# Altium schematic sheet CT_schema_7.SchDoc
size 278 x 170 mm
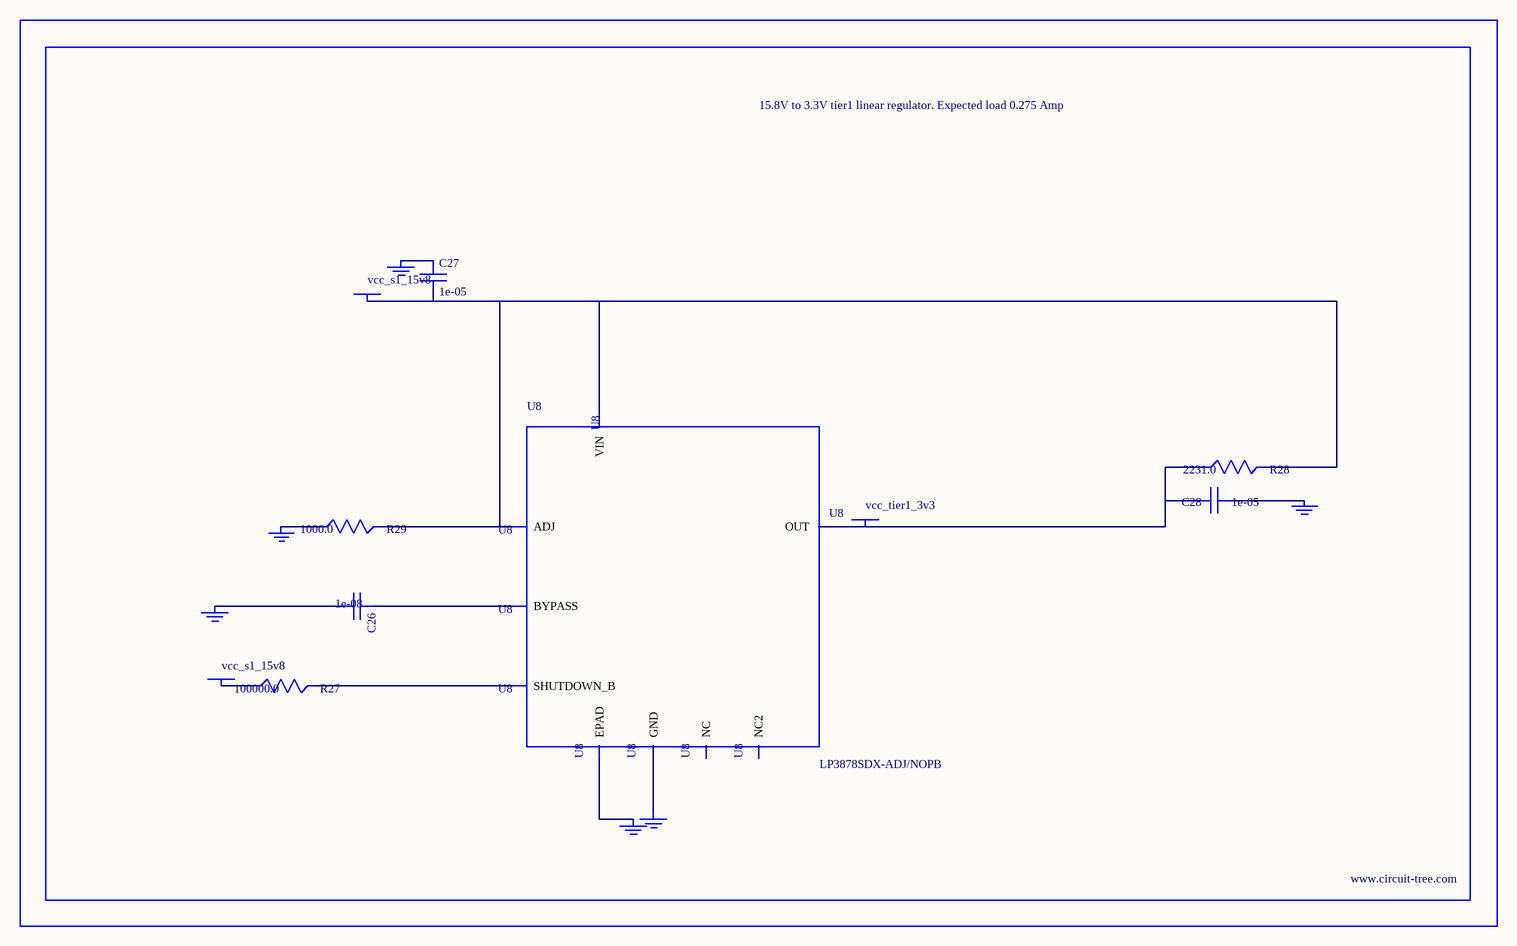
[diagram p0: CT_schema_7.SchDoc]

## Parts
BORDER6  (no value)
C26  1e-08  [C0402]
C27  1e-05  [C1210]
C28  1e-05  [C1210]
GND_INSTANCE_6_0  (no value)
GND_INSTANCE_6_1  (no value)
GND_INSTANCE_6_2  (no value)
GND_INSTANCE_6_3  (no value)
GND_INSTANCE_6_4  (no value)
GND_INSTANCE_6_5  (no value)
POWER_INSTANCE_6_0  vcc_s1_15v8
POWER_INSTANCE_6_1  vcc_s1_15v8
POWER_INSTANCE_6_2  vcc_tier1_3v3
R27  100000.0  [R0603]
R28  2231.0  [R0603]
R29  1000.0  [R0603]
U8  LP3878SDX-ADJ/NOPB  [WSON-8]

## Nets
NetC26_1: C26.1 U8.1(BYPASS)
NetC26_2: C26.2 GND_INSTANCE_6_0.0(GND)
NetC27_1: C27.1 GND_INSTANCE_6_1.0(GND)
NetC27_2: C27.2 POWER_INSTANCE_6_0.0(PWR) R28.2 R29.2 U8.4(VIN) U8.6(ADJ)
NetC28_1: C28.1 GND_INSTANCE_6_2.0(GND)
NetC28_2: C28.2 POWER_INSTANCE_6_2.0(PWR) R28.1 U8.5(OUT)
NetGND_INSTANCE_6_3_0: GND_INSTANCE_6_3.0(GND) R29.1
NetGND_INSTANCE_6_4_0: GND_INSTANCE_6_4.0(GND) U8.PAD(EPAD)
NetGND_INSTANCE_6_5_0: GND_INSTANCE_6_5.0(GND) U8.3(GND)
NetPOWER_INSTANCE_6_1_0: POWER_INSTANCE_6_1.0(PWR) R27.1
NetR27_2: R27.2 U8.8(SHUTDOWN_B)

Not connected (* = marked no-connect by the designer): U8 2(NC) 7(NC2)

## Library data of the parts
BORDER6 = BORDER_PAGE6
C26 = C0402C103K3RAC
C27 = C1210C106K5PACTU
C28 = GRM32DR61E106MA12L
GND_INSTANCE_6_0-GND_INSTANCE_6_5 = GND
POWER_INSTANCE_6_0-POWER_INSTANCE_6_2 = PWR
R27 = RC0603JR-07100KL
R28 = R28
R29 = RC0603JR-071KL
